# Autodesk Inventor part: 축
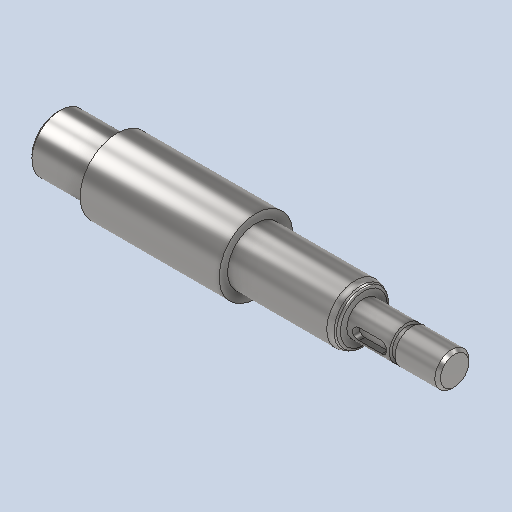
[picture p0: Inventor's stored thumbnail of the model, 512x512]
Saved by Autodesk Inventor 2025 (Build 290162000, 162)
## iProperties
Created: 2024-08
Part Number: 축
Material: 강철, 연강
Document SubType Name: Modeling
Designer: hsj03
Density: 7.86 g/cm^3
Appearance: 기본값
Author: jhkim
Sending System: Autodesk Inventor 2025
Preprocessor: ST-DEVELOPER v20
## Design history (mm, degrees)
feature "솔리드2"
node "솔리드1"
